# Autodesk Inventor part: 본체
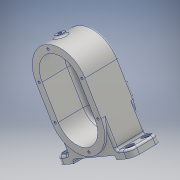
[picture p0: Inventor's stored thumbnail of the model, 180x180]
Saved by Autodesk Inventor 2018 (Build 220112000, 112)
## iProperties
Created: 2021-05
Part Number: 본체
Material: 알루미늄 6061
Document SubType Name: Modeling
Designer: Admin
Density: 2.7 g/cm^3
Appearance: 알루미늄 - 평지
Mass: 745.504 g
Surface Area: 576.419 cm^2
Volume: 276.113 cm^3
Author: Admin
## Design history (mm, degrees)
sketch "스케치1"
  geometry: L1 (56, 0)-(-56, 0) reference; L2 (0, -87.5)-(0, 87.5) reference; L3 (0, 22.5)-(0, -22.5); L4 (-40, 22.5)-(-40, -22.5); L5 (40, -22.5)-(40, 22.5); A1 r 40 centre (0, 22.5) between (40, 22.5) and (-40, 22.5); A2 r 40 centre (0, -22.5) between (-40, -22.5) and (40, -22.5); 2 further points
  constraints: 8 end point, 4 point on circle, 4 tangent, 2 centre point, 2 point on line, 1 coincident, 1 midpoint, 1 parallel
  dimensions: "d0" = 80 diameter of A2; "d1" = 45 distance of L5.start L5.end
extrude "돌출1" new body sketch "스케치1" distance "d2" = 49; taper "d3" = 0 deg
node "작업 평면1"
sketch "스케치2"
  geometry: L1 (40, -22.5)-(40, 22.5) reference; L2 (40, -22.5)-(40, -59.5); L3 (40, -59.5)-(61, -59.5); L4 (61, -59.5)-(61, -69.5); L5 (61, -69.5)-(-61, -69.5); L6 (-61, -69.5)-(-61, -59.5); L7 (-61, -59.5)-(-40, -59.5); L8 (-40, -59.5)-(-40, -22.5); L9 (0, -87.9)-(0, 40.9) reference; A1 r 40 centre (0, -22.5) between (-40, -22.5) and (40, -22.5) reference; A2 r 40 centre (0, -22.5) between (-40, -22.5) and (40, -22.5); 1 further point
  constraints: 14 end point, 5 perpendicular, 2 point on circle, 2 point on line, 1 centre point, 1 coincident, 1 tangent, 1 vertical, 1 other
  dimensions: "d5" = 122 distance between parallel lines of L6 L4; "d6" = 10 distance between parallel lines of L5 L3; "d7" = 47 distance from line of L5 A1.centre
extrude "돌출2" join sketch "스케치2" distance "d8" = 43; taper "d9" = 0 deg
sketch "스케치3"
  geometry: L1 (61, -69.5)-(-61, -69.5) reference; L2 (-35, -64.5)-(35, -64.5); L3 (35, -64.5)-(35, -69.5); L4 (35, -69.5)-(-35, -69.5); L5 (-35, -69.5)-(-35, -64.5); L6 (0, -95.9)-(0, 88.9) reference; 1 further point
  constraints: 8 end point, 2 parallel, 1 horizontal, 1 perpendicular, 1 point on line, 1 other
  dimensions: "d10" = 70 distance between parallel lines of L3 L5; "d11" = 5 distance between parallel lines of L1 L2
extrude "돌출3" cut sketch "스케치3" extent not by distance; stored distance "d12" = 46; taper "d13" = 0 deg
node "작업 평면2"
sketch "스케치4"
  geometry: C1 r 6 at (0, 21); 1 further point
  constraints: 1 centre point, 1 vertical alignment
  dimensions: "d15" = 12 diameter of C1; "d16" = 21 distance of point (0, 0) C1.centre
extrude "돌출4" join sketch "스케치4" stored distance "d17" = 46; taper "d18" = 0 deg
fillet "모깎기1" dims "d19" = 3
sketch "스케치5"
  geometry: A1 r 6 centre (0, 21) between (0, 15) and (0, 27) reference; A2 r 6 centre (0, 21) between (0, 27) and (0, 15) reference; 2 further points
  constraints: 1 coincident
  node "투영된 루프1"
sketch "스케치7"
  geometry: L1 (35, -12.8)-(35, 55.8) reference; L2 (75, -3)-(-5, -3) reference; C1 r 6 at (35, 18); 1 further point
  constraints: 1 centre point, 1 point on line
  dimensions: "d20" = 12 diameter of C1; "d21" = 21 distance from line of C1.centre L2
extrude "돌출5" cut sketch "스케치7" distance "d22" = 1; taper "d23" = 0 deg
hole "구멍1" sketch "스케치5" diameter "d24" = 4.917; stored, may be unused: countersink angle "d28" = 90 deg, drill point angle "d30" = 0 deg; dims "d25" = 12, "d26" = 4, "d27" = 2, "d29" = 17.1
sketch "스케치8"
  geometry: L1 (0, -22.5)-(0, 22.5); L2 (26, -22.5)-(26, 22.5); L3 (-26, 22.5)-(-26, -22.5); A1 r 26 centre (0, -22.5) between (-26, -22.5) and (26, -22.5); A2 r 26 centre (0, 22.5) between (26, 22.5) and (-26, 22.5); 2 further points
  constraints: 8 end point, 4 point on circle, 4 tangent, 2 centre point, 1 coincident, 1 midpoint, 1 parallel
  dimensions: "d31" = 52 diameter of A2; "d32" = 45 distance of L1.end L1.start
extrude "돌출6" join sketch "스케치8" distance "d33" = 8; taper "d34" = 0 deg
sketch "스케치9"
  geometry: L1 (26, -22.5)-(26, 22.5) reference; L2 (-26, 22.5)-(-26, -22.5) reference; L3 (26, 22.5)-(26, -22.5) reference; L4 (26, 22.5)-(26, 7.5); L5 (26, 7.5)-(-26, 7.5); L6 (-26, -22.5)-(-26, 22.5) reference; L7 (-26, 7.5)-(-26, 22.5); L8 (-26, -22.5)-(-26, 22.5) reference; L9 (26, 22.5)-(26, -22.5) reference; L10 (-40, 22.5)-(-40, -22.5) reference; L11 (40, -22.5)-(40, 22.5) reference; A1 r 26 centre (0, 22.5) between (26, 22.5) and (-26, 22.5) reference; A2 r 26 centre (0, -22.5) between (-26, -22.5) and (26, -22.5) reference; A3 r 26 centre (0, -22.5) between (-26, -22.5) and (26, -22.5) reference; A4 r 26 centre (0, 22.5) between (26, 22.5) and (-26, 22.5) reference; A5 r 40 centre (0, -22.5) between (-40, -22.5) and (40, -22.5) reference; A6 r 26 centre (0, 22.5) between (26, 22.5) and (-26, 22.5) reference; A7 r 26 centre (0, 22.5) between (26, 22.5) and (26, 22.5); A8 r 40 centre (0, 22.5) between (40, 22.5) and (-40, 22.5) reference; 2 further points
  constraints: 6 end point, 2 coincident, 2 point on circle, 2 point on line, 1 centre point, 1 collinear, 1 horizontal alignment, 1 perpendicular, 3 other
  dimensions: "d35" = 30 distance from line of L5 A2.centre
extrude "돌출7" join sketch "스케치9" distance "d36" = 3; taper "d37" = 0 deg
sketch "스케치10"
  geometry: L1 (0, 22.5)-(0, -22.5); L2 (2.458, -63.5)-(2.458, 65.5) reference; L3 (-30, 22.5)-(-30, -22.5); L4 (30, -22.5)-(30, 22.5); A1 r 30 centre (0, 22.5) between (30, 22.5) and (-30, 22.5); A2 r 30 centre (0, -22.5) between (-30, -22.5) and (30, -22.5); 2 further points
  constraints: 8 end point, 4 point on circle, 4 tangent, 2 centre point, 2 parallel, 1 coincident, 1 midpoint
  dimensions: "d38" = 60 diameter of A2; "d39" = 45 distance of L1.end L1.start
extrude "돌출8" cut sketch "스케치10" distance "d40" = 41; taper "d41" = 0 deg
sketch "스케치11"
  geometry: L1 (-85.4, 0)-(85.4, 0) reference; C1 r 14 at (0, 22.5); C2 r 14 at (0, -22.5); 1 further point
  constraints: 2 centre point, 1 symmetric about line, 1 vertical alignment
  dimensions: "d42" = 28 diameter of C1; "d43" = 28 diameter of C2; "d44" = 45 distance of C2.centre C1.centre
extrude "돌출9" cut sketch "스케치11" distance "d45" = 8; taper "d46" = 0 deg
sketch "스케치12"
  geometry: 2 further points
  constraints: 5 other
extrude "돌출10" cut sketch "스케치12" distance "d47" = 4; taper "d48" = 0 deg
sketch "스케치13"
  geometry: C1 r 14 at (0, 0) reference; C2 r 11 at (0, 0); 1 further point
  constraints: 1 centre point, 1 coincident
  dimensions: "d49" = 22 diameter of C2
extrude "돌출11" cut sketch "스케치13" extent not by distance; stored distance "d50" = 4; taper "d51" = 0 deg
sketch "스케치14"
  geometry: C1 r 10 at (0, 0); 1 further point
  constraints: 1 centre point
  dimensions: "d52" = 20 diameter of C1
extrude "돌출12" cut sketch "스케치14" distance "d53" = 4; taper "d54" = 0 deg
fillet "모깎기2" dims "d55" = 3
sketch "스케치15"
  geometry: L1 (0, 22.5)-(0, -22.5); L2 (-35, 22.5)-(-35, -22.5); L3 (35, -22.5)-(35, 22.5); A1 r 35 centre (0, 22.5) between (35, 22.5) and (-35, 22.5); A2 r 35 centre (0, -22.5) between (-35, -22.5) and (35, -22.5); 8 further points
  constraints: 8 end point, 6 point on circle, 5 coincident, 4 tangent, 2 centre point, 1 midpoint, 1 parallel, 1 vertical
  dimensions: "d56" = 70 diameter of A2; "d57" = 45 distance of L1.end L1.start
hole "구멍2" sketch "스케치15" at (-35, 22.5), (-35, -22.5), (0, -57.5), (35, -22.5), (35, 22.5), (0, 57.5) diameter "d58" = 3.242; stored, may be unused: countersink angle "d62" = 90 deg, drill point angle "d64" = 118 deg; dims "d59" = 8, "d60" = 4, "d61" = 2, "d63" = 10
fillet "모깎기3" dims "d65" = 10
sketch "스케치17"
  geometry: C1 r 5.5 at (-11, 33); C2 r 5.5 at (-11, 10); C3 r 5.5 at (91, 33); C4 r 5.5 at (91, 10); A1 r 10 centre (-11, 33) between (-11, 43) and (-21, 33) reference; A2 r 10 centre (-11, 10) between (-21, 10) and (-11, 0) reference; A3 r 10 centre (91, 33) between (101, 33) and (91, 43) reference; A4 r 10 centre (91, 10) between (91, 0) and (101, 10) reference; 1 further point
  constraints: 4 centre point, 4 coincident
  dimensions: "d66" = 11 diameter of C1; "d67" = 11 diameter of C2; "d68" = 11 diameter of C3; "d69" = 11 diameter of C4
extrude "돌출13" cut sketch "스케치17" distance "d70" = 2; taper "d71" = 0 deg
sketch "스케치19"
  geometry: C1 r 5.5 at (0, 0) reference; C2 r 5.5 at (0, -23) reference; C3 r 5.5 at (102, -23) reference; C4 r 5.5 at (102, 0) reference; C5 r 3.3 at (0, 0); C6 r 3.3 at (0, -23); C7 r 3.3 at (102, 0); C8 r 3.3 at (102, -23); 1 further point
  constraints: 4 centre point, 4 coincident
  dimensions: "d73" = 6.6 diameter of C5; "d74" = 6.6 diameter of C6; "d75" = 6.6 diameter of C7; "d76" = 6.6 diameter of C8
extrude "돌출14" cut sketch "스케치19" extent not by distance; stored distance "d77" = 2; taper "d78" = 0 deg
fillet "모깎기4" dims "d79" = 3
fillet "모깎기5" dims "d80" = 3
fillet "모깎기6" dims "d81" = 3
chamfer "모따기1" distance "d82" = 1; stored, may be unused: second distance "d83" = 2, angle "d84" = 45 deg
fillet "모깎기7" dims "d85" = 5
sketch "스케치20" dims "d86" = 40
  geometry: C1 r 11 at (0, -22.5) reference; 3 further points
  constraints: 1 coincident, 1 vertical alignment, 2 other
hole "구멍3" sketch "스케치20" at (0, -42.5) diameter "d87" = 3.242; stored, may be unused: countersink angle "d91" = 90 deg, drill point angle "d93" = 118 deg; dims "d88" = 8, "d89" = 4, "d90" = 2, "d92" = 10
node "작업 평면3"
sketch "스케치22"
  geometry: L1 (-51, -69.5)-(-35, -69.5) reference; 2 further points
  constraints: 1 vertical alignment, 1 other
  dimensions: "d98" = 12 distance from line of L1 point (0, -57.5)
feature "엠보싱1" sketch "스케치22" dims "d6" = 10, "d99" = 0.5, "d100" = 0
fillet "모깎기9" dims "d102" = 0.3
fillet "모깎기10" dims "d103" = 3
node "솔리드1"
pattern_circular "원형 패턴1" dims angle "d95" = 360 deg
node "투영된 루프2"
node "투영된 루프3"
other parameters: "d4" = 3, "d14" = 65.5
